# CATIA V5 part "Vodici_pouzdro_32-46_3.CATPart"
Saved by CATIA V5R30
Part number: Vodici_pouzdro_32-46_3
Definition: E 1100_30-46
Nomenclature: E 1100_30-46
Source: Unknown
Description: PART--DESC
Bounding box of the stored display mesh (mm): x 163.7 to 210.3, y -160.3 to -113.7, z -101 to -46
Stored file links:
  E:\Bakalarka\Model\Forma_v7\Vodici_pouzdro_32-46_3.CATPart
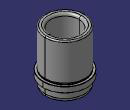
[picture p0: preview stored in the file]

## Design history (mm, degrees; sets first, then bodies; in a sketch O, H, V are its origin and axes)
Body1 "MANIFOLD_SOLID_BREP #3938" (main body)
  Solid1: solid without history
